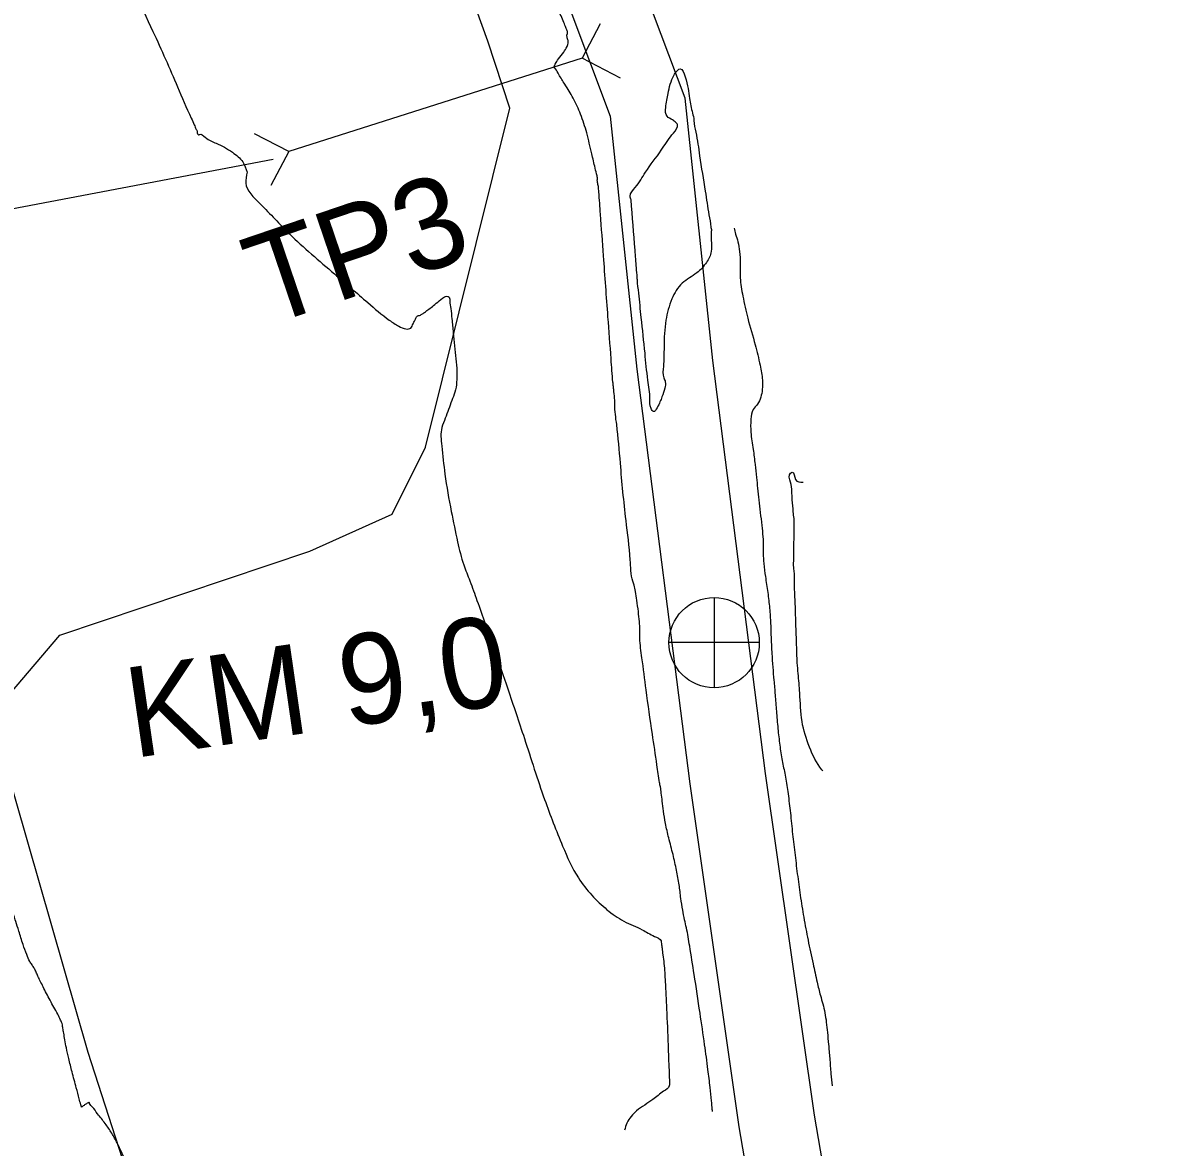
# Model space of a CAD drawing. Extents: x -478232 to -472707, y -1118753 to -1113967.
# Drawn here: x -476243.5 to -476117.8, y -1117141.4 to -1117016.9 of the extents above; entities that cross this region are included whole.
import ezdxf

# ---------------------------------------------------------------- set-up
doc = ezdxf.new("R2010")
doc.units = 0
for name, color, linetype in [('ObPÚ', 7, 'Continuous'), ('příkop', 7, 'Continuous'), ('staničení toku', 7, 'Continuous'), ('TP_stavajicí_mosty', 7, 'Continuous'), ('vodní plochy', 7, 'Continuous'), ('Vrstevnice_hlavni', 7, 'Continuous'), ('Vrstevnice_vedlejsi', 7, 'Continuous')]:
    doc.layers.add(name, color=color, linetype=linetype)

msp = doc.modelspace()

# ---------------------------------------------------------------- linework, layer by layer
at = {"layer": 'ObPÚ'}
msp.add_lwpolyline([(-476231.32, -1117146.23), (-476236.27, -1117130.89), (-476247.01, -1117093.59), (-476239.42, -1117084.68), (-476211.73, -1117075.38), (-476202.62, -1117071.28), (-476198.91, -1117063.87), (-476198.91, -1117063.87), (-476189.59, -1117026.33), (-476192, -1117018.92), (-476203.93, -1116985.93), (-476220.32, -1116954.06), (-476224.82, -1116942.7), (-476235.08, -1116917.09), (-476243.37, -1116897.27), (-476244.9, -1116886.57), (-476247.65, -1116887.11), (-476248.8, -1116851.56), (-476249.04, -1116893.61), (-476326.63, -1116908.47), (-476339.71, -1116869.87), (-476350.95, -1116836.63), (-476357.4, -1116837.74), (-476422.93, -1116845.91)], dxfattribs=at)
at = {"layer": 'příkop'}
msp.add_line((-476274.988, -1117043.208), (-476215.805, -1117031.992), dxfattribs=at)
at = {"layer": 'staničení toku'}
for p, q in [((-476166.96, -1117080.52), (-476166.96, -1117090.52)), ((-476161.96, -1117085.52), (-476171.96, -1117085.52))]:
    msp.add_line(p, q, dxfattribs=at)
msp.add_circle((-476166.96, -1117085.52), 5, dxfattribs=at)
at = {"layer": 'TP_stavajicí_mosty'}
for p, q in [((-476179.594, -1117017.011), (-476181.556, -1117020.798)), ((-476181.556, -1117020.798), (-476214.06, -1117031.14)), ((-476181.556, -1117020.798), (-476214.06, -1117031.14)), ((-476177.325, -1117023.028), (-476181.556, -1117020.798)), ((-476214.06, -1117031.14), (-476217.849, -1117029.183)), ((-476214.06, -1117031.14), (-476216.055, -1117034.906))]:
    msp.add_line(p, q, dxfattribs=at)
at = {"layer": 'vodní plochy'}
for points in [[(-476226.591, -1116759.508), (-476233.031, -1116820.563), (-476234.839, -1116830.738), (-476239.473, -1116862.842), (-476241.054, -1116885.449), (-476237.552, -1116904.211), (-476219.926, -1116948.75), (-476197.554, -1116986.509), (-476185.01, -1117009.8), (-476178.454, -1117027.217), (-476175.516, -1117055.259), (-476169.64, -1117101.16), (-476164.216, -1117139.146), (-476155.629, -1117189.113), (-476151.336, -1117200.415), (-476144.105, -1117217.145), (-476127.944, -1117246.546), (-476126.587, -1117261.477), (-476126.248, -1117271.88), (-476127.83, -1117290.877), (-476130.77, -1117309.424), (-476146.817, -1117341.989), (-476156.309, -1117361.66)], [(-476148.691, -1117365.336), (-476139.214, -1117345.696), (-476122.616, -1117312.014), (-476119.427, -1117291.891), (-476117.778, -1117272.094), (-476118.141, -1117260.956), (-476119.68, -1117244.02), (-476136.499, -1117213.422), (-476143.496, -1117197.234), (-476147.431, -1117186.874), (-476155.859, -1117137.831), (-476161.257, -1117100.025), (-476167.113, -1117054.281), (-476170.155, -1117025.255), (-476177.294, -1117006.289), (-476190.188, -1116982.346), (-476212.307, -1116945.014), (-476229.386, -1116901.857), (-476232.54, -1116884.96), (-476231.056, -1116863.743), (-476226.487, -1116832.083), (-476224.65, -1116821.748), (-476218.166, -1116760.281)]]:
    msp.add_lwpolyline(points, dxfattribs=at)
at = {"layer": 'Vrstevnice_hlavni'}
msp.add_spline([(-476206.652, -1117178.906), (-476206.912, -1117178.348), (-476209.341, -1117173.725), (-476211.536, -1117169.856), (-476213.496, -1117166.739), (-476215.223, -1117164.376), (-476216.372, -1117162.765), (-476216.944, -1117161.906), (-476216.939, -1117161.798), (-476216.948, -1117161.695), (-476216.97, -1117161.597), (-476217.006, -1117161.504), (-476217.035, -1117161.434), (-476217.055, -1117161.387), (-476217.068, -1117161.364), (-476217.869, -1117160.487), (-476219.458, -1117158.755), (-476221.836, -1117156.168), (-476224.025, -1117153.59), (-476226.026, -1117151.021), (-476227.839, -1117148.461), (-476229.316, -1117146.439), (-476230.458, -1117144.956), (-476231.265, -1117144.011), (-476231.967, -1117143.022), (-476232.564, -1117141.99), (-476233.057, -1117140.915), (-476233.666, -1117139.839), (-476234.391, -1117138.762), (-476235.231, -1117137.684), (-476235.806, -1117136.941), (-476236.117, -1117136.531), (-476236.162, -1117136.455), (-476236.279, -1117136.467), (-476236.468, -1117136.566), (-476236.728, -1117136.753), (-476236.903, -1117136.876), (-476236.994, -1117136.936), (-476237.001, -1117136.931), (-476237.008, -1117136.923), (-476237.014, -1117136.912), (-476237.021, -1117136.898), (-476237.036, -1117136.855), (-476237.059, -1117136.783), (-476237.089, -1117136.682), (-476237.266, -1117136.022), (-476237.588, -1117134.805), (-476238.057, -1117133.03), (-476238.423, -1117131.552), (-476238.688, -1117130.371), (-476238.85, -1117129.488), (-476238.979, -1117128.769), (-476239.073, -1117128.213), (-476239.134, -1117127.822), (-476239.32, -1117127.303), (-476239.632, -1117126.656), (-476240.07, -1117125.882), (-476240.487, -1117125.12), (-476240.885, -1117124.371), (-476241.262, -1117123.634), (-476241.579, -1117122.995), (-476241.836, -1117122.453), (-476242.033, -1117122.009), (-476242.251, -1117121.588), (-476242.49, -1117121.19), (-476242.749, -1117120.815), (-476243.08, -1117120.066), (-476243.481, -1117118.944), (-476243.953, -1117117.449), (-476244.291, -1117116.381), (-476244.494, -1117115.74), (-476244.561, -1117115.526), (-476244.665, -1117115.217), (-476244.806, -1117114.813), (-476244.984, -1117114.313), (-476245.236, -1117113.882), (-476245.562, -1117113.52), (-476245.962, -1117113.226), (-476246.483, -1117112.711), (-476247.125, -1117111.974), (-476247.888, -1117111.015), (-476248.249, -1117110.238), (-476248.209, -1117109.642), (-476247.766, -1117109.227), (-476247.681, -1117108.981), (-476247.952, -1117108.903), (-476248.581, -1117108.994), (-476249.094, -1117108.824), (-476249.493, -1117108.392)], degree=3, dxfattribs=at)
at = {"layer": 'Vrstevnice_vedlejsi'}
for points in [[(-476316.243, -1116908.48), (-476314.561, -1116908.998), (-476313.123, -1116909.665), (-476311.928, -1116910.479), (-476310.975, -1116911.441), (-476307.447, -1116912.926), (-476301.342, -1116914.935), (-476292.661, -1116917.468), (-476286.431, -1116920.344), (-476282.653, -1116923.565), (-476281.326, -1116927.13), (-476278.825, -1116928.622), (-476275.148, -1116928.043), (-476270.296, -1116925.391), (-476267.359, -1116923.353), (-476266.337, -1116921.926), (-476267.229, -1116921.113), (-476266.831, -1116920.277), (-476265.141, -1116919.419), (-476262.159, -1116918.539), (-476258.731, -1116917.573), (-476254.857, -1116916.522), (-476250.536, -1116915.385), (-476247.506, -1116914.708), (-476245.767, -1116914.49), (-476245.318, -1116914.73), (-476244.967, -1116914.931), (-476244.714, -1116915.09), (-476244.558, -1116915.209), (-476244.297, -1116915.426), (-476243.929, -1116915.74), (-476243.455, -1116916.152), (-476242.992, -1116916.618), (-476242.539, -1116917.137), (-476242.097, -1116917.711), (-476241.648, -1116918.268), (-476241.19, -1116918.809), (-476240.724, -1116919.335), (-476240.357, -1116919.802), (-476240.09, -1116920.212), (-476239.921, -1116920.565), (-476239.776, -1116920.901), (-476239.653, -1116921.22), (-476239.554, -1116921.522), (-476239.275, -1116922.323), (-476238.817, -1116923.622), (-476238.18, -1116925.419), (-476237.671, -1116926.892), (-476237.289, -1116928.04), (-476237.035, -1116928.865), (-476237.012, -1116929.601), (-476237.222, -1116930.251), (-476237.665, -1116930.812), (-476238.042, -1116931.305), (-476238.354, -1116931.728), (-476238.601, -1116932.083), (-476239.32, -1116932.842), (-476240.511, -1116934.008), (-476242.173, -1116935.579), (-476243.89, -1116939.165), (-476245.66, -1116944.767), (-476247.485, -1116952.383), (-476247.667, -1116959.217), (-476246.206, -1116965.267), (-476243.103, -1116970.535), (-476240.745, -1116976.442), (-476239.133, -1116982.988), (-476238.266, -1116990.175), (-476237.639, -1116995.076), (-476237.25, -1116997.694), (-476237.099, -1116998.028), (-476236.956, -1116998.362), (-476236.818, -1116998.698), (-476236.687, -1116999.033), (-476236.643, -1116999.341), (-476236.684, -1116999.621), (-476236.813, -1116999.873), (-476235.592, -1117002.993), (-476233.023, -1117008.983), (-476229.104, -1117017.842), (-476226.381, -1117023.996), (-476224.854, -1117027.447), (-476224.521, -1117028.193), (-476224.304, -1117028.701), (-476224.204, -1117028.973), (-476224.22, -1117029.007), (-476224.213, -1117029.062), (-476224.183, -1117029.137), (-476224.131, -1117029.234), (-476224.075, -1117029.288), (-476224.014, -1117029.297), (-476223.948, -1117029.262), (-476223.307, -1117029.574), (-476222.09, -1117030.231), (-476220.296, -1117031.233), (-476219.154, -1117032.301), (-476218.662, -1117033.435)], [(-476179.724, -1117035.627), (-476179.75, -1117035.303), (-476179.782, -1117035.021), (-476179.82, -1117034.78), (-476179.865, -1117034.582), (-476179.89, -1117034.419), (-476179.894, -1117034.292), (-476179.878, -1117034.199), (-476179.879, -1117034.093), (-476179.896, -1117033.973), (-476179.929, -1117033.839), (-476180.135, -1117032.979), (-476180.515, -1117031.393), (-476181.068, -1117029.081), (-476181.748, -1117027.028), (-476182.554, -1117025.234), (-476183.488, -1117023.699), (-476184.151, -1117022.618), (-476184.543, -1117021.993), (-476184.665, -1117021.823), (-476184.551, -1117021.459), (-476184.202, -1117020.899), (-476183.616, -1117020.145), (-476183.252, -1117019.523), (-476183.11, -1117019.034), (-476183.19, -1117018.678), (-476183.244, -1117018.432), (-476183.271, -1117018.296), (-476183.272, -1117018.269), (-476183.261, -1117018.232), (-476183.237, -1117018.185), (-476183.201, -1117018.126), (-476183.188, -1117018.039), (-476183.199, -1117017.923), (-476183.234, -1117017.779), (-476183.365, -1117017.428), (-476183.592, -1117016.87), (-476183.916, -1117016.106), (-476184.647, -1117015.105), (-476185.785, -1117013.867), (-476187.33, -1117012.392), (-476188.388, -1117011.262), (-476188.958, -1117010.478), (-476189.041, -1117010.039), (-476189.106, -1117009.636), (-476189.153, -1117009.267), (-476189.182, -1117008.935), (-476189.557, -1117008.114), (-476190.278, -1117006.805), (-476191.346, -1117005.008), (-476192.127, -1117003.633), (-476192.621, -1117002.68), (-476192.828, -1117002.148), (-476193.262, -1117001.482), (-476193.923, -1117000.684), (-476194.811, -1116999.752), (-476195.507, -1116998.877), (-476196.011, -1116998.058), (-476196.323, -1116997.295), (-476196.58, -1116996.639), (-476196.782, -1116996.088), (-476196.93, -1116995.644), (-476197.398, -1116994.17), (-476198.187, -1116991.667), (-476199.296, -1116988.134), (-476200.094, -1116985.612), (-476200.58, -1116984.1), (-476200.756, -1116983.599), (-476200.905, -1116983.191), (-476201.028, -1116982.876), (-476201.124, -1116982.653), (-476201.204, -1116982.463), (-476201.268, -1116982.305), (-476201.315, -1116982.181), (-476202.111, -1116980.963), (-476203.654, -1116978.651), (-476205.945, -1116975.246), (-476207.511, -1116972.904), (-476208.351, -1116971.625), (-476208.466, -1116971.41), (-476208.609, -1116971.129), (-476208.78, -1116970.784), (-476208.979, -1116970.373), (-476209.684, -1116969.095), (-476210.895, -1116966.948), (-476212.612, -1116963.934), (-476214.062, -1116961.433), (-476215.245, -1116959.445), (-476216.162, -1116957.97), (-476216.798, -1116956.955), (-476217.154, -1116956.399), (-476217.228, -1116956.303), (-476217.294, -1116956.22), (-476217.349, -1116956.15), (-476217.396, -1116956.094), (-476218.104, -1116955.211), (-476219.474, -1116953.504)], [(-476176.161, -1117036.513), (-476175.718, -1117042.074), (-476175.564, -1117044.01), (-476175.479, -1117045.102), (-476175.461, -1117045.349), (-476175.311, -1117046.825), (-476175.028, -1117049.53), (-476174.614, -1117053.465), (-476174.295, -1117056.457), (-476174.071, -1117058.506), (-476173.943, -1117059.613), (-476173.677, -1117059.948), (-476173.274, -1117059.512), (-476172.734, -1117058.304), (-476172.431, -1117057.352), (-476172.366, -1117056.656), (-476172.538, -1117056.216), (-476172.585, -1117054.93), (-476172.507, -1117052.798), (-476172.304, -1117049.82), (-476171.633, -1117047.459), (-476170.492, -1117045.715), (-476168.883, -1117044.587), (-476167.811, -1117043.42), (-476167.276, -1117042.212), (-476167.277, -1117040.965), (-476167.282, -1117040.123), (-476167.288, -1117039.686), (-476167.298, -1117039.655), (-476167.306, -1117039.615), (-476167.313, -1117039.564), (-476167.319, -1117039.504), (-476167.531, -1117038.16), (-476167.948, -1117035.533), (-476168.572, -1117031.623), (-476168.988, -1117029.013), (-476169.197, -1117027.703), (-476169.197, -1117027.693), (-476169.357, -1117026.885), (-476169.677, -1117025.278), (-476170.156, -1117022.874), (-476170.711, -1117021.98), (-476171.342, -1117022.599), (-476172.05, -1117024.729), (-476172.323, -1117026.279), (-476172.161, -1117027.249), (-476171.565, -1117027.64), (-476171.177, -1117027.959), (-476170.999, -1117028.206), (-476171.029, -1117028.383), (-476171.632, -1117029.313), (-476172.807, -1117030.997), (-476174.556, -1117033.436), (-476175.706, -1117035.133), (-476176.257, -1117036.087), (-476176.161, -1117036.513)], [(-476218.662, -1117033.435), (-476218.822, -1117034.635), (-476217.263, -1117036.911), (-476213.986, -1117040.265), (-476208.992, -1117044.695), (-476205.309, -1117047.877), (-476202.938, -1117049.809), (-476201.877, -1117050.493), (-476201.083, -1117050.788), (-476200.555, -1117050.695), (-476200.293, -1117050.212), (-476200.099, -1117049.847), (-476199.974, -1117049.597), (-476199.917, -1117049.464), (-476199.835, -1117049.37), (-476199.726, -1117049.313), (-476199.592, -1117049.295), (-476199.387, -1117049.198), (-476199.112, -1117049.021), (-476198.765, -1117048.765), (-476198.307, -1117048.409), (-476197.736, -1117047.953), (-476197.054, -1117047.397), (-476196.575, -1117047.173), (-476196.299, -1117047.28), (-476196.227, -1117047.719), (-476196.128, -1117048.519), (-476196.001, -1117049.68), (-476195.846, -1117051.202), (-476195.702, -1117052.674), (-476195.567, -1117054.097), (-476195.442, -1117055.471), (-476195.474, -1117056.701), (-476195.663, -1117057.787), (-476196.008, -1117058.731), (-476196.365, -1117059.696), (-476196.731, -1117060.685), (-476197.109, -1117061.695), (-476197.123, -1117063.752), (-476196.775, -1117066.855), (-476196.063, -1117071.005), (-476195.366, -1117074.361), (-476194.682, -1117076.923), (-476194.013, -1117078.692), (-476193.219, -1117080.86), (-476192.302, -1117083.427), (-476191.26, -1117086.392), (-476189.817, -1117090.625), (-476187.973, -1117096.125), (-476185.729, -1117102.894), (-476183.735, -1117108.045), (-476181.992, -1117111.578), (-476180.498, -1117113.494), (-476178.823, -1117115.088), (-476176.965, -1117116.361), (-476174.925, -1117117.312), (-476173.551, -1117118.042), (-476172.843, -1117118.55), (-476172.8, -1117118.837), (-476172.731, -1117119.351), (-476172.637, -1117120.093), (-476172.517, -1117121.062), (-476172.381, -1117123.052), (-476172.229, -1117126.063), (-476172.059, -1117130.096), (-476171.954, -1117132.864), (-476171.913, -1117134.367), (-476171.937, -1117134.606), (-476172.55, -1117135.185), (-476173.752, -1117136.105), (-476175.544, -1117137.365), (-476176.609, -1117138.711), (-476176.875, -1117139.506)], [(-476167.154, -1117137.424), (-476167.161, -1117137.225), (-476167.247, -1117136.247), (-476167.406, -1117134.768), (-476167.64, -1117132.789), (-476168.012, -1117130.045), (-476168.521, -1117126.535), (-476169.167, -1117122.259), (-476169.669, -1117119.115), (-476170.025, -1117117.1), (-476170.236, -1117116.217), (-476170.442, -1117115.129), (-476170.643, -1117113.838), (-476170.838, -1117112.343), (-476171.127, -1117110.728), (-476171.51, -1117108.993), (-476171.987, -1117107.138), (-476172.343, -1117105.532), (-476172.58, -1117104.177), (-476172.697, -1117103.072), (-476172.807, -1117102.176), (-476172.909, -1117101.489), (-476173.004, -1117101.011), (-476173.299, -1117099.062), (-476173.794, -1117095.642), (-476174.488, -1117090.75), (-476174.951, -1117087.207), (-476175.181, -1117085.013), (-476175.18, -1117084.167), (-476175.236, -1117083.188), (-476175.348, -1117082.077), (-476175.517, -1117080.833), (-476175.674, -1117079.86), (-476175.821, -1117079.16), (-476175.956, -1117078.731), (-476176.254, -1117076.34), (-476176.715, -1117071.985), (-476177.338, -1117065.667), (-476177.752, -1117061.381), (-476177.957, -1117059.126), (-476177.954, -1117058.902), (-476177.964, -1117058.642), (-476177.989, -1117058.344), (-476178.028, -1117058.009), (-476178.071, -1117057.621), (-476178.119, -1117057.181), (-476178.171, -1117056.687), (-476178.37, -1117054.109), (-476178.715, -1117049.446), (-476179.207, -1117042.699), (-476179.543, -1117038.092), (-476179.724, -1117035.627)], [(-476164.738, -1117039.618), (-476164.589, -1117040.298), (-476164.326, -1117041.14), (-476164.151, -1117042.226), (-476164.062, -1117043.554), (-476164.06, -1117045.125), (-476163.785, -1117047.145), (-476163.236, -1117049.615), (-476162.414, -1117052.533), (-476161.872, -1117054.816), (-476161.609, -1117056.464), (-476161.626, -1117057.476), (-476161.805, -1117058.357), (-476162.145, -1117059.107), (-476162.646, -1117059.726), (-476162.895, -1117060.769), (-476162.892, -1117062.236), (-476162.636, -1117064.128), (-476162.427, -1117065.792), (-476162.265, -1117067.228), (-476162.15, -1117068.436), (-476162.014, -1117069.726), (-476161.857, -1117071.1), (-476161.679, -1117072.556), (-476161.565, -1117073.797), (-476161.516, -1117074.823), (-476161.53, -1117075.635), (-476161.452, -1117076.765), (-476161.282, -1117078.213), (-476161.02, -1117079.978), (-476160.827, -1117081.715), (-476160.704, -1117083.424), (-476160.65, -1117085.104), (-476160.571, -1117086.708), (-476160.468, -1117088.238), (-476160.341, -1117089.693), (-476160.203, -1117091.313), (-476160.056, -1117093.096), (-476159.9, -1117095.044), (-476159.688, -1117096.874), (-476159.423, -1117098.585), (-476159.103, -1117100.177), (-476158.81, -1117102.014), (-476158.544, -1117104.095), (-476158.304, -1117106.421), (-476158.038, -1117108.76), (-476157.747, -1117111.115), (-476157.43, -1117113.483), (-476157.035, -1117115.932), (-476156.562, -1117118.46), (-476156.012, -1117121.068), (-476155.555, -1117123.114), (-476155.192, -1117124.597), (-476154.924, -1117125.518), (-476154.705, -1117126.505), (-476154.536, -1117127.559), (-476154.417, -1117128.679), (-476154.292, -1117130.005), (-476154.162, -1117131.535), (-476154.026, -1117133.271), (-476153.901, -1117134.584)], [(-476154.938, -1117099.703), (-476155.022, -1117099.605), (-476156.404, -1117097.091), (-476157.223, -1117094.255), (-476157.477, -1117091.097), (-476157.652, -1117088.93), (-476157.747, -1117087.756), (-476157.763, -1117087.573), (-476157.809, -1117086.347), (-476157.886, -1117084.076), (-476157.993, -1117080.762), (-476158.071, -1117078.504), (-476158.121, -1117077.302), (-476158.143, -1117077.157), (-476158.148, -1117076.515), (-476158.136, -1117075.376), (-476158.107, -1117073.739), (-476158.094, -1117072.596), (-476158.097, -1117071.945), (-476158.116, -1117071.786), (-476158.191, -1117071.037), (-476158.32, -1117069.696), (-476158.504, -1117067.763), (-476158.503, -1117066.747), (-476158.317, -1117066.647), (-476157.946, -1117067.462), (-476157.085, -1117067.749)], [(-476223.981, -1117207.237), (-476224.285, -1117206.855), (-476224.501, -1117206.557), (-476224.628, -1117206.343), (-476224.668, -1117206.213), (-476224.801, -1117205.902), (-476225.026, -1117205.411), (-476225.345, -1117204.739), (-476225.578, -1117204.261), (-476225.727, -1117203.975), (-476225.791, -1117203.883), (-476225.875, -1117203.662), (-476225.98, -1117203.311), (-476226.105, -1117202.831), (-476226.229, -1117202.417), (-476226.352, -1117202.067), (-476226.475, -1117201.782), (-476226.572, -1117201.501), (-476226.643, -1117201.224), (-476226.689, -1117200.951), (-476227.057, -1117200.755), (-476227.747, -1117200.637), (-476228.759, -1117200.595), (-476229.446, -1117200.566), (-476229.808, -1117200.548), (-476229.845, -1117200.544), (-476229.875, -1117200.547), (-476229.898, -1117200.559), (-476229.914, -1117200.578), (-476229.923, -1117200.586), (-476229.927, -1117200.583), (-476229.925, -1117200.567), (-476229.926, -1117200.55), (-476229.93, -1117200.533), (-476229.937, -1117200.515), (-476230.309, -1117199.985), (-476231.045, -1117198.942), (-476232.146, -1117197.387), (-476233.138, -1117195.885), (-476234.022, -1117194.438), (-476234.797, -1117193.044), (-476236.35, -1117190.18), (-476238.683, -1117185.847), (-476241.794, -1117180.043), (-476244.171, -1117175.438), (-476245.814, -1117172.033), (-476246.723, -1117169.826), (-476247.372, -1117168.01), (-476247.761, -1117166.585), (-476247.891, -1117165.55), (-476248.161, -1117164.525), (-476248.57, -1117163.508), (-476249.119, -1117162.501), (-476249.598, -1117161.498), (-476250.007, -1117160.498), (-476250.346, -1117159.503), (-476250.69, -1117158.53), (-476251.038, -1117157.58), (-476251.39, -1117156.652), (-476251.803, -1117155.599), (-476252.277, -1117154.423), (-476252.812, -1117153.123), (-476253.36, -1117151.76), (-476253.922, -1117150.336), (-476254.497, -1117148.85), (-476255.085, -1117147.257), (-476255.684, -1117145.558), (-476256.294, -1117143.752), (-476259.267, -1117141.777), (-476264.603, -1117139.631), (-476272.302, -1117137.316), (-476278.025, -1117135.721), (-476281.773, -1117134.847), (-476283.545, -1117134.694), (-476286.438, -1117134.211), (-476290.451, -1117133.398), (-476295.585, -1117132.255), (-476301.704, -1117130.929), (-476308.808, -1117129.42), (-476316.898, -1117127.729), (-476324.767, -1117125.966), (-476332.416, -1117124.134), (-476339.844, -1117122.232), (-476344.627, -1117120.838), (-476346.763, -1117119.952), (-476346.254, -1117119.574), (-476345.231, -1117118.402), (-476343.693, -1117116.434), (-476341.642, -1117113.672), (-476338.379, -1117110.142), (-476333.906, -1117105.844), (-476328.223, -1117100.779), (-476323.405, -1117096.497), (-476319.453, -1117093.001), (-476316.366, -1117090.289), (-476314.122, -1117087.639), (-476312.721, -1117085.051)]]:
    msp.add_spline(points, degree=3, dxfattribs=at)

# ---------------------------------------------------------------- texts
at = {"layer": 'staničení toku'}
msp.add_text('KM 9,0', height=10, rotation=8.23446, dxfattribs=at).set_placement((-476231.274, -1117098.309))
at = {"layer": 'TP_stavajicí_mosty'}
msp.add_text('TP3', height=10, rotation=18.78552, dxfattribs=at).set_placement((-476216.63, -1117050.56))

doc.saveas('drawing.dxf')
